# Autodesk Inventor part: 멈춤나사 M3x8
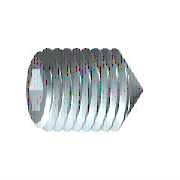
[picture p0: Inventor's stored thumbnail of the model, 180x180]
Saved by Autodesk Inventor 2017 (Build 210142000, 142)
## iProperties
Created: 2012-02
Part Number: 멈춤나사 M3x8
Material: 강철, 연강
Description: 6각 소켓 머리 없는 멈춤 나사
Document SubType Name: Modeling
Standard: KS B 1028
Designer: mduedu
Standards Organization: KS
Language: ko-KR
Size Designation: 원추점 M3x8
Categories: <MemberInstance><Categories><Category DisplayName="조임쇠" InternalName="e4da775c-781d-43d5-af7c-5136215cf5a6" Mnemonic="FSTN"><Category DisplayName="볼트" InternalN
Density: 7.86 g/cm^3
Mass: 0.360339 g
Surface Area: 0.888172 cm^2
Volume: 0.0458447 cm^3
Appearance: 강철
IsCustomPart: 1
Author: mduedu
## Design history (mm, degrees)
sketch "스케치1"
  geometry: L1 (0, 0)-(5.5, 0); L2 (8, 0.866)-(8, 1.5); L3 (8, 1.5)-(0, 1.5); L4 (8, 0.866)-(6, 0.866); L5 (6, 0.866)-(5.5, 0); L6 (0, -0.3)-(0, 1.8) reference; L7 (0, 1.5)-(0, 0)
  constraints: 13 end point, 3 parallel, 1 collinear, 1 perpendicular, 1 point on line
  dimensions: "d0" = 2 distance of L2.start L4.end (= INTI); "d1" = 60 deg angle of L5 L1; "d2" = 3 diameter of L3 L1 (= NND); "d3" = 1.73205 diameter of L4 L1 (= 1.1547 x SW); "d5" = 8 distance from line of L2 L3.end (= NLG)
revolve "본체" sketch "스케치1" stored, may be unused: angle "d6" = 90 deg
sketch "스케치2"
  geometry: L1 (-0.433, 0.75)-(0.433, 0.75); L2 (0.433, 0.75)-(0.866, 0); L3 (0.866, 0)-(0.433, -0.75); L4 (0.433, -0.75)-(-0.433, -0.75); L5 (-0.433, -0.75)-(-0.866, 0); L6 (-0.866, 0)-(-0.433, 0.75); 3 further points
  constraints: 12 end point, 1 coincident, 1 horizontal, 13 other
extrude "슬롯" join sketch "스케치2" taper "d7" = 0 deg; stored distance "d21" = 10
workaxis "Work Axis1"
workplane "Work Plane1"
sketch "스케치5"
  geometry: L1 (-4, -0.15)-(-2.65, -1.5) reference; L2 (-4, 0.15)-(-2.65, 1.5) reference; L3 (-2.65, 1.5)-(-4.15, 0); L4 (-2.65, -1.5)-(-4.15, 0); 1 further point
  constraints: 4 end point, 1 horizontal alignment, 1 perpendicular
node "작업점1"
body "Solid1"
feature "스레드" dims "d12" = 8 (= NLG), "d13" = 0
chamfer "모따기1" distance "d8" = 1.35 (computed from NND, SPD, FAWI); stored, may be unused: angle "d9" = 45 deg (= FAWI), second distance "d34" = 1.35 (computed from NND, SPD, FAWI)
chamfer "모따기2" distance "d10" = 0.30673 (= -0.5 x GD1 + 0.5 x NND); stored, may be unused: angle "d11" = 45 deg (= FAWI), second distance "d35" = 0.30673 (= -0.5 x GD1 + 0.5 x NND)
other parameters: "NND" = 3 [user parameter; used in 5 equation terms], "NLG" = 8 [user parameter; used in 2 equation terms], "INTI" = 2 [user parameter; used in 1 equation term], "FAWI" = 45 deg [user parameter; used in 4 equation terms], "SW" = 1.5 [user parameter; used in 2 equation terms], "GD1" = 2.38655 (= THREADDIA - 1.2269 x PTC) [user parameter; used in 2 equation terms], "d4" = 0, "FAWI1" = 45 deg [user parameter], "SPD" = 0.3 [user parameter; used in 2 equation terms], "d36" = 0, "d37" = 0, "GUL" = 0.30673 (= 0.61345 x PTC) [user parameter], "TOA" = 30 deg [user parameter], "THREADDIA" = 3 [user parameter; used in 1 equation term], "PTC" = 0.5 [user parameter; used in 4 equation terms], "GAL" = 0.30673 (= 0.61345 x PTC) [user parameter], "E0" = 1.7325 (= 1.155 x SW) [user parameter]
